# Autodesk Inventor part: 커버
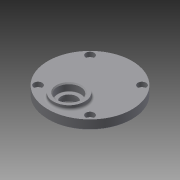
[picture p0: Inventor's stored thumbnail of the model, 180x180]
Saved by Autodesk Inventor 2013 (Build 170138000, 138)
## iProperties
Created: 2015-07
Part Number: 커버
Material: 일반
Document SubType Name: Modeling
Designer: user
Density: 1 g/cm^3
Author: user
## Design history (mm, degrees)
sketch "스케치1"
  geometry: C1 r 40 at (0, 0); 1 further point
  constraints: 1 centre point, 1 coincident
  dimensions: "d0" = 80 diameter of C1
extrude "돌출1" new body sketch "스케치1" distance "d1" = 9; taper "d2" = 0 deg
sketch "스케치2"
  geometry: L1 (0, 0)-(0, -20); C1 r 40 at (0, 0) reference; C2 r 15 at (0, -20)
  constraints: 2 end point, 1 centre point, 1 coincident, 1 vertical
  dimensions: "d3" = 20 distance of L1.start L1.end; "d4" = 30 diameter of C2
extrude "돌출2" join sketch "스케치2" distance "d5" = 4; taper "d6" = 0 deg
sketch "스케치3"
  geometry: L1 (0, 0)-(0, 11); L2 (0, 0)-(0, -20); C1 r 40 at (0, 0) reference; C2 r 14 at (0, 11); C3 r 14 at (0, -20)
  constraints: 4 end point, 2 centre point, 2 coincident, 1 collinear, 1 vertical
  dimensions: "d7" = 11 distance of L1.start L1.end; "d8" = 20 distance of L1.start L2.end; "d9" = 28 diameter of C2; "d10" = 28 diameter of C3
extrude "돌출3" join sketch "스케치3" distance "d11" = 3; taper "d12" = 0 deg
sketch "스케치4"
  geometry: C1 r 14 at (0, 0) reference; C2 r 14 at (0, -31) reference; C3 r 11 at (0, 0); 1 further point
  constraints: 1 centre point, 1 coincident
  dimensions: "d13" = 22 diameter of C3
extrude "돌출4" cut sketch "스케치4" distance "d14" = 7; taper "d15" = 0 deg
sketch "스케치5"
  geometry: C1 r 9 at (0, 0); 2 further points
  constraints: 1 centre point, 1 coincident, 1 vertical alignment
  dimensions: "d16" = 18 diameter of C1
extrude "돌출5" cut sketch "스케치5" distance "d17" = 1; taper "d18" = 0 deg
sketch "스케치6"
  geometry: C1 r 14 at (0, 0) reference; C2 r 11 at (0, 0); 1 further point
  constraints: 1 centre point, 1 coincident
  dimensions: "d19" = 22 diameter of C2
extrude "돌출6" cut sketch "스케치6" distance "d20" = 7; taper "d21" = 0 deg
sketch "스케치7"
  geometry: C1 r 11 at (0, 0) reference; C2 r 7.5 at (0, 0); 1 further point
  constraints: 1 centre point, 1 coincident
  dimensions: "d22" = 15 diameter of C2
extrude "돌출7" cut sketch "스케치7" distance "d23" = 2; taper "d24" = 0 deg
sketch "스케치8"
  geometry: C1 r 15 at (0, 0) reference; C2 r 11 at (0, 0); 1 further point
  constraints: 1 centre point, 1 coincident
  dimensions: "d25" = 22 diameter of C2
extrude "돌출8" cut sketch "스케치8" distance "d26" = 7; taper "d27" = 0 deg
fillet "모깎기1" dims "d28" = 2
fillet "모깎기2" dims "d29" = 0.3
fillet "모깎기3" dims "d30" = 2
chamfer "모따기1" distance "d31" = 1; stored, may be unused: second distance "d32" = 2, angle "d33" = 45 deg
chamfer "모따기2" distance "d34" = 1; stored, may be unused: second distance "d35" = 2, angle "d36" = 45 deg
sketch "스케치9" dims "d37" = 70
  geometry: L1 (0, 0)-(24.749, 24.749); L2 (0, 0)-(35, 0); C1 r 40 at (0, 0) reference; 1 further point
  constraints: 4 end point, 2 coincident, 1 equal length, 1 horizontal, 3 other
  dimensions: "d38" = 45 deg angle of L2 L1
hole "구멍1" sketch "스케치9" at (24.749, 24.749) diameter "d39" = 4.5; stored, may be unused: countersink angle "d43" = 90 deg, drill point angle "d45" = 0 deg; dims "d40" = 6, "d41" = 8, "d42" = 4.4, "d44" = 9
node "솔리드1"
pattern_circular "원형 패턴1" dims angle "d47" = 360 deg
node "절단 모서리 투영1"
